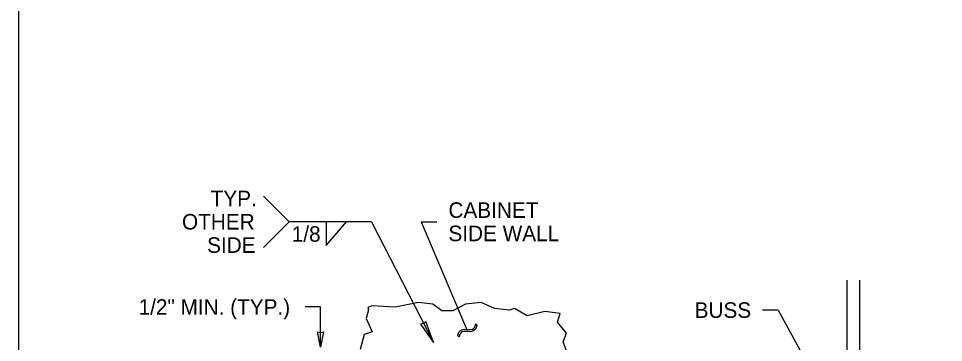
# Model space of a CAD drawing. Extents: x 99862 to 103680, y 99470 to 105076.
# Drawn here: x 99862 to 100816, y 103636 to 103969 of the extents above; entities that cross this region are included whole.
import ezdxf

# ---------------------------------------------------------------- set-up
doc = ezdxf.new("R2010")
doc.units = 0
for name, color, linetype in [('Level 1', 7, 'Continuous'), ('Level 15', 7, 'Continuous'), ('Level 20', 7, 'Continuous'), ('Level 40', 7, 'Continuous')]:
    doc.layers.add(name, color=color, linetype=linetype)

msp = doc.modelspace()

# ---------------------------------------------------------------- linework, layer by layer
at = {"layer": 'Level 1'}
msp.add_lwpolyline([(99862, 102999.5), (103151, 102999.5), (103151, 105075.5), (99862, 105075.5)], close=True, dxfattribs=at)
at = {"layer": 'Level 15'}
for p, q in [((100277.21, 103760.18), (100293.21, 103760.18)), ((100277.21, 103760.18), (100324.64, 103648.37)), ((100173.37, 103672.5), (100157.37, 103672.5)), ((100173.37, 103631.31), (100173.37, 103672.5)), ((100644.96, 103669.27), (100628.96, 103669.27)), ((100644.96, 103669.27), (100676, 103613.09)), ((100317.53, 103648.26), (100318.96, 103649.09)), ((100318.96, 103649.09), (100321.35, 103649.7)), ((100321.35, 103649.7), (100325.44, 103649.46)), ((100325.44, 103649.46), (100327.99, 103649.38)), ((100327.99, 103649.38), (100329.86, 103649.78)), ((100329.86, 103649.78), (100331.01, 103650.47)), ((100331.88, 103648.59), (100330.36, 103647.7)), ((100331.01, 103650.47), (100331.94, 103651.46)), ((100333.05, 103649.83), (100331.88, 103648.59)), ((100331.94, 103651.46), (100332.75, 103653)), ((100332.75, 103653), (100333.56, 103655.28)), ((100333.89, 103651.41), (100333.05, 103649.83)), ((100333.56, 103655.28), (100334.38, 103653.34)), ((100334.38, 103653.34), (100333.89, 103651.41)), ((100314.96, 103643.46), (100315.58, 103645.52)), ((100315.78, 103641.51), (100314.96, 103643.46)), ((100315.58, 103645.52), (100316.42, 103647.08)), ((100317.19, 103644.93), (100315.78, 103641.51)), ((100316.42, 103647.08), (100317.53, 103648.26)), ((100318.23, 103646.21), (100317.19, 103644.93)), ((100319.42, 103646.99), (100318.23, 103646.21)), ((100320.88, 103647.35), (100319.42, 103646.99)), ((100323.3, 103647.25), (100320.88, 103647.35)), ((100327.71, 103647.09), (100323.3, 103647.25)), ((100330.36, 103647.7), (100327.71, 103647.09))]:
    msp.add_line(p, q, dxfattribs=at)
for points in [[(100289.63, 103635.99), (100281.84, 103657.65), (100279.67, 103655.35), (100276.53, 103654.92)], [(100173.37, 103631.31), (100170.29, 103647.04), (100173.37, 103646.31), (100176.46, 103647.04)]]:
    msp.add_lwpolyline(points, close=True, dxfattribs=at)
at = {"layer": 'Level 40'}
for p, q in [((100141.18, 103760.18), (100114.68, 103786.68)), ((100141.18, 103760.18), (100114.68, 103733.68)), ((100225.76, 103760.18), (100141.18, 103760.18)), ((100179.01, 103735.83), (100200.05, 103760.18)), ((100179.01, 103760.18), (100179.01, 103735.83)), ((100225.76, 103760.18), (100289.63, 103635.99)), ((100715.82, 103700.17), (100715.82, 103274.68)), ((100728.96, 103700.17), (100728.96, 103274.68))]:
    msp.add_line(p, q, dxfattribs=at)
for points in [[(100420.54, 103665.74), (100404.43, 103667.75), (100386.34, 103663.29), (100373.43, 103671.04), (100368.26, 103669.32), (100352.77, 103671.04), (100338.99, 103677.07), (100322.64, 103675.35), (100309.73, 103668.45), (100298.53, 103668.45), (100289.07, 103675.35), (100274.43, 103677.07), (100250.29, 103672.24)], [(100221.97, 103672.05), (100222.92, 103669.52), (100220.42, 103660.73), (100226.53, 103647.09), (100218.23, 103644.29), (100214.31, 103628.79)], [(100250.29, 103672.24), (100226.22, 103673.62), (100221.97, 103672.05)], [(100426.81, 103627.53), (100423.3, 103636.66), (100427.03, 103645.57), (100417.68, 103657.04), (100420.54, 103665.74)]]:
    msp.add_lwpolyline(points, dxfattribs=at)

# ---------------------------------------------------------------- texts
at = {"layer": 'Level 20'}
for s, p in [('TYP.', (100060.07, 103776.18)), ('OTHER', (100030.55, 103752.18)), ('SIDE', (100056.45, 103728.18)), ('1/2" MIN. (TYP.)', (99985.83, 103664.5)), ('BUSS', (100559, 103661.27))]:
    msp.add_text(s, height=16, rotation=360, dxfattribs=at).set_placement(p)
for s, p in [('CABINET ', (100305.21, 103764.18)), ('1/8', (100143.7, 103739.62)), ('SIDE WALL', (100305.21, 103740.18))]:
    msp.add_text(s, height=16, dxfattribs=at).set_placement(p)

doc.saveas('drawing.dxf')
